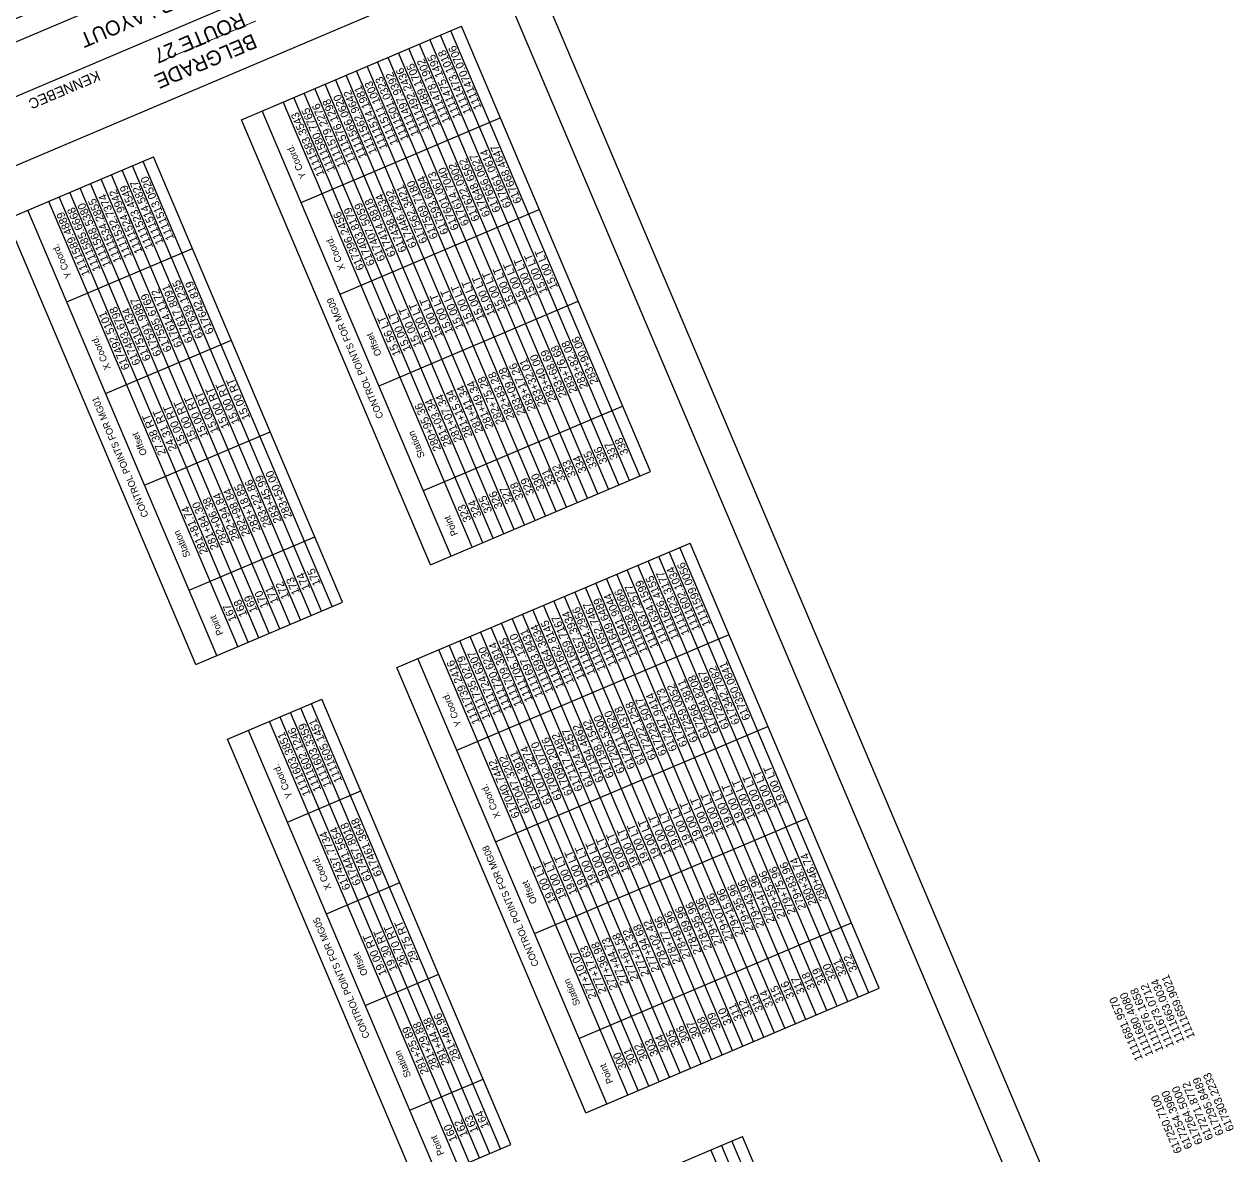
# Model space of a CAD drawing. Extents: x 1111260 to 1112147, y 617053 to 618212.
# Drawn here: x 1111569 to 1112100, y 617467 to 617963 of the extents above; entities that cross this region are included whole.
import ezdxf

# ---------------------------------------------------------------- set-up
doc = ezdxf.new("R2010")
doc.units = 0
for name, color, linetype in [('ANNOTATION', 7, 'Continuous'), ('BORDER', 7, 'Continuous'), ('BRIDGE_TITLE', 7, 'Continuous'), ('H_V CONTROLS', 7, 'Continuous'), ('HIGHWAY_TITLE', 7, 'Continuous'), ('PLOT BOUNDARY', 7, 'Continuous')]:
    doc.layers.add(name, color=color, linetype=linetype)

msp = doc.modelspace()

# ---------------------------------------------------------------- linework, layer by layer
at = {"layer": 'BORDER'}
for p, q in [((1111755.5, 618035.73), (1111272.23, 617830.6)), ((1112068.1, 617299.33), (1111755.51, 618035.74)), ((1111718.09, 617995.9), (1111557, 617927.52)), ((1111775.03, 617989.7), (1111291.77, 617784.57))]:
    msp.add_line(p, q, dxfattribs=at)
at = {"layer": 'H_V CONTROLS'}
for p, q in [((1111664.44, 617920.92), (1111761.09, 617961.95)), ((1111844.12, 617766.34), (1111761.09, 617961.95)), ((1111844.12, 617766.34), (1111761.09, 617961.95)), ((1111830.31, 617760.48), (1111747.28, 617956.09)), ((1111834.91, 617762.44), (1111751.88, 617958.04)), ((1111839.52, 617764.39), (1111756.49, 617960)), ((1111821.11, 617756.57), (1111738.08, 617952.18)), ((1111825.71, 617758.53), (1111742.68, 617954.14)), ((1111807.3, 617750.71), (1111724.27, 617946.32)), ((1111811.9, 617752.67), (1111728.87, 617948.27)), ((1111816.5, 617754.62), (1111733.47, 617950.23)), ((1111793.49, 617744.85), (1111710.46, 617940.46)), ((1111798.09, 617746.81), (1111715.06, 617942.41)), ((1111802.7, 617748.76), (1111719.67, 617944.37)), ((1111779.68, 617738.99), (1111696.65, 617934.6)), ((1111784.29, 617740.94), (1111701.26, 617936.55)), ((1111788.89, 617742.9), (1111705.86, 617938.51)), ((1111770.48, 617735.08), (1111687.45, 617930.69)), ((1111775.08, 617737.04), (1111692.05, 617932.64)), ((1111756.67, 617729.22), (1111673.64, 617924.83)), ((1111765.88, 617733.13), (1111682.85, 617928.74)), ((1111747.47, 617725.32), (1111664.44, 617920.92)), ((1111690.74, 617884.56), (1111778.18, 617921.68)), ((1111561.42, 617877.19), (1111625.85, 617904.55)), ((1111704.28, 617706.98), (1111621.25, 617902.59)), ((1111708.88, 617708.94), (1111625.85, 617904.55)), ((1111708.88, 617708.94), (1111625.85, 617904.55)), ((1111695.08, 617703.08), (1111612.05, 617898.68)), ((1111699.68, 617705.03), (1111616.65, 617900.64)), ((1111681.27, 617697.22), (1111598.24, 617892.82)), ((1111685.87, 617699.17), (1111602.84, 617894.78)), ((1111690.47, 617701.12), (1111607.44, 617896.73)), ((1111667.46, 617691.36), (1111584.43, 617886.96)), ((1111672.06, 617693.31), (1111589.03, 617888.92)), ((1111676.67, 617695.26), (1111593.64, 617890.87)), ((1111662.86, 617689.4), (1111579.83, 617885.01)), ((1111707.83, 617844.29), (1111795.28, 617881.41)), ((1111644.45, 617681.59), (1111561.42, 617877.19)), ((1111653.65, 617685.49), (1111570.62, 617881.1)), ((1111587.72, 617840.83), (1111642.95, 617864.27)), ((1111724.93, 617804.01), (1111812.37, 617841.13)), ((1111604.81, 617800.56), (1111660.04, 617824)), ((1111744.46, 617757.99), (1111831.91, 617795.11)), ((1111621.91, 617760.29), (1111677.14, 617783.73)), ((1111747.47, 617725.32), (1111844.12, 617766.34)), ((1111641.44, 617714.26), (1111696.67, 617737.7)), ((1111732.73, 617680.24), (1111861.6, 617734.94)), ((1111940.03, 617537.38), (1111857, 617732.99)), ((1111944.63, 617539.33), (1111861.6, 617734.94)), ((1111944.63, 617539.33), (1111861.6, 617734.94)), ((1111930.82, 617533.47), (1111847.79, 617729.08)), ((1111935.43, 617535.42), (1111852.4, 617731.03)), ((1111917.02, 617527.61), (1111833.99, 617723.22)), ((1111921.62, 617529.56), (1111838.59, 617725.17)), ((1111926.22, 617531.52), (1111843.19, 617727.12)), ((1111903.21, 617521.75), (1111820.18, 617717.36)), ((1111907.81, 617523.7), (1111824.78, 617719.31)), ((1111912.41, 617525.66), (1111829.38, 617721.26)), ((1111889.4, 617515.89), (1111806.37, 617711.49)), ((1111894, 617517.84), (1111810.97, 617713.45)), ((1111898.61, 617519.79), (1111815.58, 617715.4)), ((1111644.45, 617681.59), (1111708.88, 617708.94)), ((1111880.2, 617511.98), (1111797.17, 617707.59)), ((1111884.8, 617513.93), (1111801.77, 617709.54)), ((1111866.39, 617506.12), (1111783.36, 617701.73)), ((1111870.99, 617508.07), (1111787.96, 617703.68)), ((1111875.59, 617510.03), (1111792.56, 617705.63)), ((1111852.58, 617500.26), (1111769.55, 617695.87)), ((1111857.18, 617502.21), (1111774.15, 617697.82)), ((1111861.79, 617504.17), (1111778.76, 617699.77)), ((1111759.03, 617643.87), (1111878.7, 617694.67)), ((1111843.38, 617496.35), (1111760.35, 617691.96)), ((1111847.98, 617498.3), (1111764.95, 617693.91)), ((1111834.17, 617492.44), (1111751.14, 617688.05)), ((1111838.77, 617494.4), (1111755.74, 617690)), ((1111815.76, 617484.63), (1111732.73, 617680.24)), ((1111824.97, 617488.54), (1111741.94, 617684.14)), ((1111658.41, 617648.69), (1111699.84, 617666.27)), ((1111778.26, 617468.71), (1111695.23, 617664.32)), ((1111782.87, 617470.67), (1111699.84, 617666.27)), ((1111782.87, 617470.67), (1111699.84, 617666.27)), ((1111764.46, 617462.85), (1111681.43, 617658.46)), ((1111769.06, 617464.81), (1111686.03, 617660.41)), ((1111773.66, 617466.76), (1111690.63, 617662.37)), ((1111759.85, 617460.9), (1111676.82, 617656.51)), ((1111776.12, 617603.6), (1111895.79, 617654.39)), ((1111741.44, 617453.08), (1111658.41, 617648.69)), ((1111750.65, 617456.99), (1111667.62, 617652.6)), ((1111684.71, 617612.33), (1111716.93, 617626)), ((1111793.22, 617563.33), (1111912.88, 617614.12)), ((1111701.81, 617572.05), (1111734.02, 617585.73)), ((1111812.76, 617517.3), (1111932.42, 617568.1)), ((1111718.9, 617531.78), (1111751.12, 617545.46)), ((1111815.76, 617484.63), (1111944.63, 617539.33)), ((1111738.44, 617485.76), (1111770.66, 617499.43)), ((1111755.69, 617419.53), (1111884.56, 617474.23)), ((1111962.98, 617276.67), (1111879.95, 617472.28)), ((1111967.59, 617278.63), (1111884.56, 617474.23)), ((1111967.59, 617278.63), (1111884.56, 617474.23)), ((1111741.44, 617453.08), (1111782.87, 617470.67)), ((1111953.78, 617272.77), (1111870.75, 617468.37)), ((1111958.38, 617274.72), (1111875.35, 617470.33))]:
    msp.add_line(p, q, dxfattribs=at)
at = {"layer": 'PLOT BOUNDARY'}
msp.add_lwpolyline([(1112097.99, 617268.06), (1111765.87, 618050.49), (1111259.59, 617835.59), (1111591.71, 617053.16)], close=True, dxfattribs=at)

# ---------------------------------------------------------------- texts
at = {"layer": 'ANNOTATION'}
for s, height, p in [('1111473.1018', 3.5156, (1111765.58, 617924.25)), ('1111470.0706', 3.5156, (1111770.13, 617926.18)), ('1111489.1705', 3.5156, (1111751.71, 617918.36)), ('1111478.1902', 3.5156, (1111756.35, 617920.33)), ('1111475.1495', 3.5156, (1111760.92, 617922.27)), ('1111501.0323', 3.5156, (1111738.01, 617912.54)), ('1111497.9392', 3.5156, (1111742.6, 617914.49)), ('1111492.2436', 3.5156, (1111747.1, 617916.4)), ('1111514.1981', 3.5156, (1111728.73, 617908.6)), ('1111511.1003', 3.5156, (1111733.37, 617910.57)), ('1111576.1298', 3.5156, (1111714.86, 617902.72)), ('1111566.0620', 3.5156, (1111719.57, 617904.71)), ('1111562.9642', 3.5156, (1111724.09, 617906.63)), ('1111583.3543', 3.5156, (1111701.06, 617896.86)), ('1111580.7765', 3.5156, (1111705.68, 617898.82)), ('1111579.2276', 3.5156, (1111710.27, 617900.77)), ('617668.4647', 3.5156, (1111787.65, 617884.91)), ('617648.6562', 3.5156, (1111773.87, 617879.06)), ('617656.0627', 3.5156, (1111778.44, 617881)), ('617661.0614', 3.5156, (1111783.1, 617882.98)), ('617601.0673', 3.5156, (1111760.12, 617873.22)), ('617614.7040', 3.5156, (1111764.62, 617875.13)), ('617622.0902', 3.5156, (1111769.23, 617877.09)), ('1111523.4549', 3.5156, (1111625.77, 617864.9)), ('1111514.5827', 3.5156, (1111630.34, 617866.84)), ('1111513.0520', 3.5156, (1111634.95, 617868.8)), ('617562.3421', 3.5156, (1111746.25, 617867.34)), ('617569.7180', 3.5156, (1111750.89, 617869.3)), ('617593.6894', 3.5156, (1111755.53, 617871.27)), ('1111532.7374', 3.5156, (1111616.47, 617860.95)), ('1111524.9942', 3.5156, (1111621.13, 617862.93)), ('617438.8534', 3.5156, (1111737.09, 617863.45)), ('617446.2292', 3.5156, (1111741.61, 617865.37)), ('1111585.6668', 3.5156, (1111602.69, 617855.1)), ('1111568.5380', 3.5156, (1111607.26, 617857.04)), ('1111534.2855', 3.5156, (1111611.92, 617859.02)), ('617403.8179', 3.5156, (1111723.19, 617857.55)), ('617407.5059', 3.5156, (1111727.79, 617859.5)), ('617414.8818', 3.5156, (1111732.38, 617861.45)), ('1111589.4889', 3.5156, (1111597.98, 617853.1)), ('617396.2456', 3.5156, (1111718.58, 617855.59)), ('15.00 LT', 3.516, (1111799.07, 617845.37)), ('15.00 LT', 3.516, (1111803.61, 617847.3)), ('15.00 LT', 3.516, (1111785.2, 617839.48)), ('15.00 LT', 3.516, (1111789.83, 617841.45)), ('15.00 LT', 3.516, (1111794.4, 617843.39)), ('617639.1235', 3.5156, (1111647.85, 617825.57)), ('617642.819', 3.516, (1111652.47, 617827.53)), ('15.00 LT', 3.516, (1111771.49, 617833.67)), ('15.00 LT', 3.516, (1111776.08, 617835.61)), ('15.00 LT', 3.516, (1111780.58, 617837.52)), ('617595.6769', 3.5156, (1111633.98, 617819.68)), ('617614.1172', 3.5156, (1111638.65, 617821.66)), ('617617.8091', 3.5156, (1111643.28, 617823.63)), ('15.00 LT', 3.516, (1111762.21, 617829.73)), ('15.00 LT', 3.516, (1111766.85, 617831.7)), ('617591.9887', 3.5156, (1111629.44, 617817.75)), ('15.00 LT', 3.516, (1111748.34, 617823.84)), ('15.00 LT', 3.516, (1111753.05, 617825.84)), ('15.00 LT', 3.516, (1111757.57, 617827.76)), ('617492.5101', 3.5156, (1111615.5, 617811.84)), ('617493.6798', 3.5156, (1111620.21, 617813.83)), ('617510.434', 3.516, (1111624.78, 617815.77)), ('15.56 LT', 3.516, (1111734.54, 617817.98)), ('15.00 LT', 3.516, (1111739.16, 617819.94)), ('15.00 LT', 3.516, (1111743.75, 617821.89)), ('283+82.08', 3.516, (1111816.8, 617803.59)), ('283+90.06', 3.516, (1111821.35, 617805.52)), ('283+40.00', 3.516, (1111802.93, 617797.7)), ('283+68.69', 3.516, (1111807.57, 617799.67)), ('283+76.68', 3.516, (1111812.14, 617801.61)), ('283+17.26', 3.516, (1111793.82, 617793.83)), ('283+32.01', 3.516, (1111798.32, 617795.74)), ('282+75.28', 3.516, (1111779.95, 617787.94)), ('282+83.28', 3.516, (1111784.59, 617789.91)), ('283+09.28', 3.516, (1111789.23, 617791.88)), ('15.00 RT', 3.516, (1111659.25, 617786.02)), ('15.00 RT', 3.516, (1111663.82, 617787.96)), ('15.00 RT', 3.516, (1111668.43, 617789.92)), ('281+15.34', 3.516, (1111766.08, 617782.06)), ('281+41.34', 3.516, (1111770.79, 617784.06)), ('281+49.34', 3.516, (1111775.31, 617785.98)), ('15.00 RT', 3.516, (1111645.4, 617780.14)), ('15.00 RT', 3.516, (1111649.95, 617782.07)), ('15.00 RT', 3.516, (1111654.61, 617784.05)), ('280+95.36', 3.516, (1111752.28, 617776.2)), ('281+03.34', 3.516, (1111756.89, 617778.16)), ('281+07.34', 3.516, (1111761.49, 617780.11)), ('24.31 RT', 3.516, (1111636.17, 617776.23)), ('15.00 RT', 3.516, (1111640.74, 617778.16)), ('27.38 RT', 3.516, (1111631.46, 617774.23)), ('338', 3.516, (1111834.57, 617774.36)), ('335', 3.516, (1111820.8, 617768.51)), ('336', 3.516, (1111825.37, 617770.45)), ('337', 3.516, (1111830.03, 617772.43)), ('333', 3.516, (1111811.54, 617764.58)), ('334', 3.516, (1111816.16, 617766.54)), ('283+45.99', 3.516, (1111682.22, 617744.61)), ('283+50.00', 3.516, (1111686.83, 617746.57)), ('330', 3.516, (1111797.81, 617758.75)), ('331', 3.516, (1111802.45, 617760.72)), ('332', 3.516, (1111807.04, 617762.67)), ('283+18.85', 3.516, (1111673.01, 617740.7)), ('283+22.86', 3.516, (1111677.65, 617742.67)), ('328', 3.516, (1111788.54, 617754.81)), ('329', 3.516, (1111793.17, 617756.78)), ('282+06.38', 3.516, (1111659.14, 617734.82)), ('282+94.84', 3.516, (1111663.8, 617736.8)), ('282+98.84', 3.516, (1111668.35, 617738.72)), ('325', 3.516, (1111774.71, 617748.95)), ('326', 3.516, (1111779.3, 617750.9)), ('327', 3.516, (1111784.01, 617752.89)), ('281+81.74', 3.516, (1111649.86, 617730.88)), ('281+84.30', 3.516, (1111654.57, 617732.88)), ('323', 3.516, (1111765.5, 617745.04)), ('324', 3.516, (1111770.12, 617747)), ('175', 3.516, (1111699.4, 617716.98)), ('1111602.1034', 3.5156, (1111866.02, 617697.2)), ('1111599.0056', 3.5156, (1111870.66, 617699.17)), ('172', 3.516, (1111685.57, 617711.11)), ('173', 3.516, (1111690.21, 617713.08)), ('174', 3.516, (1111694.78, 617715.02)), ('1111634.1599', 3.5156, (1111852.27, 617691.37)), ('1111626.4155', 3.5156, (1111856.82, 617693.3)), ('1111623.3177', 3.5156, (1111861.43, 617695.26)), ('169', 3.516, (1111671.7, 617705.22)), ('170', 3.516, (1111676.36, 617707.2)), ('171', 3.516, (1111680.91, 617709.13)), ('1111641.9044', 3.5156, (1111838.45, 617685.5)), ('1111638.8066', 3.5156, (1111843.02, 617687.44)), ('1111637.2577', 3.5156, (1111847.65, 617689.41)), ('167', 3.516, (1111662.43, 617701.28)), ('168', 3.516, (1111667.13, 617703.28)), ('1111654.2956', 3.5156, (1111824.53, 617679.59)), ('1111652.7467', 3.5156, (1111829.31, 617681.62)), ('1111649.6489', 3.5156, (1111833.81, 617683.53)), ('1111662.8145', 3.5156, (1111810.73, 617673.73)), ('1111659.7167', 3.5156, (1111815.46, 617675.74)), ('1111657.3934', 3.5156, (1111820.06, 617677.69)), ('1111693.8431', 3.5156, (1111801.62, 617669.87)), ('1111664.3634', 3.5156, (1111806.23, 617671.82)), ('1111709.3814', 3.5156, (1111787.86, 617664.03)), ('1111705.7545', 3.5156, (1111792.5, 617666)), ('1111697.1210', 3.5156, (1111797.02, 617667.92)), ('1111735.0279', 3.5156, (1111773.92, 617658.11)), ('1111724.6307', 3.5156, (1111778.63, 617660.11)), ('1111720.6230', 3.5156, (1111783.27, 617662.08)), ('1111739.2416', 3.5156, (1111769.35, 617656.17)), ('617342.7082', 3.5156, (1111883.54, 617655.94)), ('617350.0841', 3.5156, (1111888.18, 617657.91)), ('617266.3811', 3.5156, (1111869.79, 617650.1)), ('617284.8208', 3.5156, (1111874.33, 617652.03)), ('617292.1967', 3.5156, (1111878.95, 617653.99)), ('617247.9414', 3.5156, (1111855.96, 617644.23)), ('617255.3173', 3.5156, (1111860.53, 617646.17)), ('617259.0052', 3.5156, (1111865.17, 617648.14)), ('617222.1258', 3.5156, (1111846.83, 617640.35)), ('617229.5017', 3.5156, (1111851.33, 617642.26)), ('617205.5300', 3.5156, (1111832.98, 617634.48)), ('617211.0620', 3.5156, (1111837.57, 617636.42)), ('617218.4378', 3.5156, (1111842.05, 617638.32)), ('1111602.1246', 3.5156, (1111699.64, 617626.58)), ('1111603.3359', 3.5156, (1111704.18, 617628.51)), ('1111605.1451', 3.5156, (1111708.84, 617630.49)), ('617194.4662', 3.5156, (1111823.75, 617630.56)), ('617198.1542', 3.5156, (1111828.25, 617632.47)), ('1111603.3851', 3.5156, (1111694.98, 617624.6)), ('617092.0770', 3.5156, (1111805.38, 617622.76)), ('617099.2076', 3.5156, (1111810.02, 617624.73)), ('617117.2482', 3.5156, (1111814.54, 617626.65)), ('617124.5457', 3.5156, (1111819.13, 617628.6)), ('617064.3911', 3.5156, (1111796.15, 617618.84)), ('617071.3274', 3.5156, (1111800.79, 617620.81)), ('617040.7442', 3.5156, (1111786.87, 617614.9)), ('617047.3202', 3.5156, (1111791.44, 617616.84)), ('19.00 LT', 3.516, (1111894.91, 617616.38)), ('19.00 LT', 3.516, (1111899.5, 617618.33)), ('19.00 LT', 3.516, (1111904.14, 617620.3)), ('19.00 LT', 3.516, (1111881.14, 617610.53)), ('19.00 LT', 3.516, (1111885.75, 617612.49)), ('19.00 LT', 3.516, (1111890.3, 617614.42)), ('19.00 LT', 3.516, (1111871.93, 617606.62)), ('19.00 LT', 3.516, (1111876.5, 617608.56)), ('19.00 LT', 3.516, (1111858.01, 617600.72)), ('19.00 LT', 3.516, (1111862.79, 617602.74)), ('19.00 LT', 3.516, (1111867.29, 617604.65)), ('617457.8018', 3.5156, (1111721.7, 617587.24)), ('617461.3648', 3.5156, (1111726.36, 617589.22)), ('19.00 LT', 3.516, (1111844.21, 617594.86)), ('19.00 LT', 3.516, (1111848.94, 617596.87)), ('19.00 LT', 3.516, (1111853.54, 617598.82)), ('617437.7734', 3.5156, (1111712.49, 617583.33)), ('617441.5654', 3.5156, (1111717.15, 617585.31)), ('19.00 LT', 3.516, (1111830.51, 617589.04)), ('19.00 LT', 3.516, (1111835.1, 617590.99)), ('19.00 LT', 3.516, (1111839.71, 617592.95)), ('19.00 LT', 3.516, (1111821.34, 617585.15)), ('19.00 LT', 3.516, (1111825.98, 617587.12)), ('19.00 LT', 3.516, (1111807.4, 617579.23)), ('19.00 LT', 3.516, (1111812.11, 617581.23)), ('19.00 LT', 3.516, (1111816.75, 617583.2)), ('279+83.96', 3.516, (1111912.65, 617574.6)), ('280+38.74', 3.516, (1111917.24, 617576.55)), ('280+46.74', 3.516, (1111921.88, 617578.52)), ('19.00 LT', 3.516, (1111802.84, 617577.3)), ('279+55.96', 3.516, (1111903.49, 617570.71)), ('279+75.96', 3.516, (1111908.03, 617572.64)), ('279+35.96', 3.516, (1111889.66, 617564.84)), ('279+43.96', 3.516, (1111894.23, 617566.78)), ('279+47.96', 3.516, (1111898.87, 617568.75)), ('279+03.96', 3.516, (1111875.75, 617558.93)), ('279+07.96', 3.516, (1111880.53, 617560.96)), ('279+15.96', 3.516, (1111885.02, 617562.87)), ('278+81.96', 3.516, (1111861.95, 617553.08)), ('278+89.96', 3.516, (1111866.68, 617555.09)), ('278+95.96', 3.516, (1111871.27, 617557.03)), ('29.75 RT', 3.516, (1111742.33, 617551.61)), ('278+02.42', 3.516, (1111852.83, 617549.21)), ('278+77.96', 3.516, (1111857.61, 617550.79)), ('19.30 RT', 3.516, (1111733.12, 617547.7)), ('26.70 RT', 3.516, (1111737.66, 617549.63)), ('277+67.58', 3.516, (1111839.08, 617543.37)), ('277+75.32', 3.516, (1111843.72, 617545.34)), ('277+94.68', 3.516, (1111848.24, 617547.26)), ('19.00 RT', 3.516, (1111728.46, 617545.72)), ('277+17.63', 3.516, (1111824.97, 617537.83)), ('277+36.98', 3.516, (1111829.85, 617539.45)), ('277+44.73', 3.516, (1111834.49, 617541.42)), ('277+10.07', 3.516, (1111820.57, 617535.51)), ('321', 3.516, (1111930.47, 617545.39)), ('322', 3.516, (1111935.11, 617547.35)), ('319', 3.516, (1111921.26, 617541.48)), ('320', 3.516, (1111925.87, 617543.44)), ('316', 3.516, (1111907.46, 617535.62)), ('317', 3.516, (1111912.1, 617537.59)), ('318', 3.516, (1111916.71, 617539.55)), ('1111673.0712', 3.5156, (1112074.25, 617514.11)), ('1111663.0034', 3.5156, (1112078.86, 617516.07)), ('1111659.9021', 3.5156, (1112083.44, 617518.01)), ('313', 3.516, (1111893.75, 617529.8)), ('314', 3.516, (1111898.25, 617531.71)), ('315', 3.516, (1111902.89, 617533.68)), ('1111680.4080', 3.5156, (1112065.12, 617510.23)), ('1111676.1658', 3.5156, (1112069.67, 617512.17)), ('310', 3.516, (1111879.91, 617523.92)), ('311', 3.516, (1111884.5, 617525.87)), ('312', 3.516, (1111888.97, 617527.77)), ('1111681.9570', 3.5156, (1112060.52, 617508.28)), ('281+44.38', 3.516, (1111756.06, 617506.28)), ('281+46.96', 3.516, (1111760.73, 617508.26)), ('308', 3.516, (1111870.68, 617520.01)), ('309', 3.516, (1111875.17, 617521.91)), ('281+25.89', 3.516, (1111746.86, 617502.38)), ('281+29.88', 3.516, (1111751.52, 617504.35)), ('305', 3.516, (1111856.95, 617514.18)), ('306', 3.516, (1111861.47, 617516.1)), ('307', 3.516, (1111866.06, 617518.05)), ('302', 3.516, (1111843.08, 617508.29)), ('303', 3.516, (1111847.72, 617510.26)), ('304', 3.516, (1111852.31, 617512.21)), ('300', 3.516, (1111833.8, 617504.35)), ('301', 3.516, (1111838.36, 617506.29)), ('617295.8489', 3.5156, (1112096.13, 617475.39)), ('617303.2233', 3.5156, (1112100.7, 617477.33)), ('617254.3980', 3.5156, (1112082.38, 617469.56)), ('617264.5000', 3.5156, (1112086.94, 617471.49)), ('617271.8772', 3.5156, (1112091.51, 617473.43)), ('617250.7100', 3.5156, (1112077.79, 617467.61)), ('163', 3.516, (1111768.63, 617476.69)), ('164', 3.516, (1111773.29, 617478.67)), ('160', 3.516, (1111759.42, 617472.78)), ('162', 3.516, (1111764.08, 617474.76))]:
    msp.add_text(s, height=height, rotation=113, dxfattribs=at).set_placement(p)
at = {"layer": 'BORDER'}
msp.add_text('GEOMETRIC CURB LAYOUT', height=6.5214, rotation=203, dxfattribs=at).set_placement((1111700.8, 618004.17))
at = {"layer": 'BRIDGE_TITLE'}
for s, height, p in [('_____________', 4.5358, (1111671.18, 617963.24)), ('KENNEBEC', 4.536, (1111601.18, 617942.63))]:
    msp.add_text(s, height=height, rotation=203, dxfattribs=at).set_placement(p)
at = {"layer": 'H_V CONTROLS'}
for s, p in [('Y Coord.', (1111693.04, 617895.76)), ('Y Coord.', (1111590.02, 617852.03)), ('X Coord.', (1111710.14, 617855.49)), ('CONTROL POINTS FOR MG09', (1111726.94, 617790.32)), ('X Coord.', (1111607.12, 617811.76)), ('Offset', (1111726.13, 617817.81)), ('CONTROL POINTS FOR MG01', (1111623.75, 617746.98)), ('Offset', (1111623.11, 617774.09)), ('Station', (1111745.12, 617773.08)), ('Point', (1111759.65, 617738.83)), ('Station', (1111642.1, 617729.36)), ('Point', (1111656.64, 617695.11)), ('Y Coord.', (1111761.33, 617655.08)), ('Y Coord.', (1111687.02, 617623.53)), ('X Coord.', (1111778.43, 617614.8)), ('CONTROL POINTS FOR MG08', (1111795.23, 617549.63)), ('X Coord.', (1111704.11, 617583.26)), ('Offset', (1111794.42, 617577.13)), ('CONTROL POINTS FOR MG05', (1111720.91, 617518.08)), ('Offset', (1111720.11, 617545.58)), ('Station', (1111813.41, 617532.4)), ('Station', (1111739.09, 617500.85)), ('Point', (1111827.95, 617498.15)), ('Point', (1111753.63, 617466.6))]:
    msp.add_text(s, height=3, rotation=113, dxfattribs=at).set_placement(p)
at = {"layer": 'HIGHWAY_TITLE'}
for s, p in [('ROUTE 27', (1111664.54, 617968.11)), ('BELGRADE', (1111669.42, 617958.85))]:
    msp.add_text(s, height=6.521, rotation=203, dxfattribs=at).set_placement(p)

doc.saveas('drawing.dxf')
